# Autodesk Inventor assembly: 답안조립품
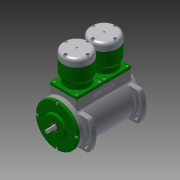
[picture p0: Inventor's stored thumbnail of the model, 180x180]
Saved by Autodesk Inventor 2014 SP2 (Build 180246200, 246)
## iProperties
Created: 2017-08
Part Number: 답안조립품
Document SubType Name: Assembly
Designer: 거성
Author: 거성
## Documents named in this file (16)
- C:\Users\거성\Desktop\370808V1019\답안조립품.iam
- C:\Users\거성\Desktop\370808V1019\본체.ipt
- C:\Users\거성\Desktop\370808V1019\앞커버.ipt
- C:\Users\거성\Desktop\370808V1019\오일 실 12 25 7.ipt
- C:\Users\거성\Desktop\370808V1019\베어링 12 x 28 x 8.ipt
- C:\Users\거성\Desktop\370808V1019\크랭크축.ipt
- C:\Users\거성\Desktop\370808V1019\커넥팅로드.ipt
- C:\Users\거성\Desktop\370808V1019\커넥팅로드 엔드.ipt
- C:\Users\거성\Desktop\370808V1019\너트 M4.ipt
- C:\Users\거성\Desktop\370808V1019\육각 머리 볼트 M4 x 16.ipt
- C:\Users\거성\Desktop\370808V1019\피스톤.ipt
- C:\Users\거성\Desktop\370808V1019\피스톤핀.ipt
- C:\Users\거성\Desktop\370808V1019\실린더.ipt
- C:\Users\거성\Desktop\370808V1019\볼트 M4 x 8.ipt
- C:\Users\거성\Desktop\370808V1019\실린더헤드.ipt
- C:\Users\거성\Desktop\370808V1019\볼트 M5 x 20.ipt
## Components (4 placed, 2 different names)
1. 피스톤:1
2. 피스톤핀:1
3. 피스톤:2
4. 피스톤핀:2
